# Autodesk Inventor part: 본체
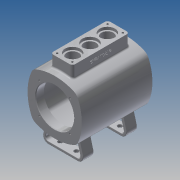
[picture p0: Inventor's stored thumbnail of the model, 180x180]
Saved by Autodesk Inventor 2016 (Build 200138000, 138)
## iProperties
Created: 2015-11
Part Number: 본체
Material: 알루미늄 6061
Document SubType Name: Modeling
Designer: mduedu
Density: 2.71 g/cm^3
Appearance: 알루미늄 - 평지
Mass: 1109.74 g
Surface Area: 1165.93 cm^2
Volume: 409.5 cm^3
Author: mduedu
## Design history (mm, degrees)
sketch "스케치2"
  geometry: L1 (0, 250)-(0, -250); L2 (250, 0)-(-250, 0); L3 (-50, 50)-(50, 50); L4 (50, 50)-(50, -50); L5 (50, -50)-(-50, -50); L6 (-50, -50)-(-50, 50); A1 r 90 centre (-40, 0) between (40.415, -40.415) and (40.415, 40.415); A2 r 90 centre (40, 0) between (-40.415, 40.415) and (-40.415, -40.415); A3 r 90 centre (0, -40) between (40.415, 40.415) and (-40.415, 40.415); A4 r 90 centre (0, 40) between (-40.415, -40.415) and (40.415, -40.415); 2 further points
  constraints: 12 end point, 8 point on circle, 4 centre point, 4 tangent, 3 perpendicular, 2 horizontal alignment, 2 midpoint, 2 parallel, 2 symmetric about line, 1 coincident, 1 equal radius, 1 horizontal, 1 vertical, 1 vertical alignment, 2 other
  dimensions: "d6" = 500 distance of L1.start L1.end; "d8" = 500 distance of L2.start L2.end; "d9" = 100 distance of L3.end L4.end; "d11" = 90 radius of A3
extrude "돌출1" new body sketch "스케치2" stored distance "d12" = 130; taper "d13" = 0 deg
fillet "모깎기6" dims "d30" = 15
feature "쉘1" dims "d31" = 15, "d32" = 6, "d33" = 15
sketch "스케치5"
  geometry: C1 r 35 at (0, 0); 1 further point
  constraints: 1 centre point, 1 coincident
  dimensions: "d34" = 70 diameter of C1
extrude "돌출3" cut sketch "스케치5" stored distance "d36" = 3; taper "d37" = 0 deg
fillet "모깎기14" dims "d78" = 3
sketch "스케치12"
  geometry: L1 (0, 0)-(28.284, 28.284); L2 (0, 0)-(40, 0); A1 r 40 centre (0, 0) between (28.284, 28.284) and (40, 0); 2 further points
  constraints: 4 end point, 2 coincident, 2 point on circle, 1 centre point, 1 horizontal
  dimensions: "d79" = 80 diameter of A1; "d80" = 45 deg angle of L2 L1
hole "구멍2" sketch "스케치12" at (28.284, 28.284) diameter "d82" = 3.242; stored, may be unused: countersink angle "d86" = 90 deg, drill point angle "d88" = 118 deg; dims "d83" = 9, "d84" = 10, "d85" = 2, "d87" = 11
node "작업 평면2"
sketch "스케치13"
  geometry: L1 (-52.5, -20)-(52.5, -20); L2 (52.5, -20)-(52.5, 20); L3 (52.5, 20)-(-52.5, 20); L4 (-52.5, 20)-(-52.5, -20); L5 (-52.5, -20)-(52.5, 20); L6 (52.5, -20)-(-52.5, 20); 1 further point
  constraints: 12 end point, 2 midpoint, 2 parallel, 1 horizontal, 1 perpendicular
  dimensions: "d93" = 105 distance of L2.end L3.end; "d95" = 40 distance of L1.end L2.end
extrude "돌출8" join sketch "스케치13" stored distance "d96" = 80; taper "d97" = 0 deg
fillet "모깎기15" dims "d98" = 5
fillet "모깎기16" dims "d99" = 3
sketch "스케치14"
  geometry: L1 (-52.5, 15)-(-52.5, -15) reference; L2 (52.5, -15)-(52.5, 15) reference; L3 (-52.5, 0)-(52.5, 0); 4 further points
  constraints: 2 end point, 2 midpoint, 2 point on line, 1 coincident
  dimensions: "d100" = 32 distance of point (-32, 0) point (0, 0); "d102" = 32 distance of point (32, 0) point (0, 0) (derived)
hole "구멍3" sketch "스케치14" at (-32, 0), (0, 0), (32, 0) diameter "d103" = 22; stored, may be unused: countersink angle "d107" = 90 deg, drill point angle "d109" = 118 deg; dims "d104" = 8, "d105" = 28, "d106" = 5, "d108" = 10
sketch "스케치15"
  geometry: L1 (46.5, -14)-(-46.5, -14); L2 (-46.5, -14)-(-46.5, 14); L3 (-46.5, 14)-(46.5, 14); L4 (46.5, 14)-(46.5, -14); L5 (46.5, -14)-(-46.5, 14); L6 (-46.5, -14)-(46.5, 14); L7 (47.5, 20)-(-47.5, 20) reference; L8 (-52.5, 15)-(-52.5, -15) reference; 5 further points
  constraints: 12 end point, 4 coincident, 2 midpoint, 2 parallel, 1 horizontal, 1 perpendicular
  dimensions: "d110" = 6 distance between parallel lines of L3 L7; "d111" = 6 distance between parallel lines of L2 L8
hole "구멍4" sketch "스케치15" at (-46.5, 14), (46.5, 14), (46.5, -14), (-46.5, -14) diameter "d112" = 3.242; stored, may be unused: countersink angle "d116" = 90 deg, drill point angle "d118" = 118 deg; dims "d113" = 10, "d114" = 28, "d115" = 5, "d117" = 13
sketch "스케치16"
  geometry: L1 (33.5, 0)-(61.5, 0) reference; 2 further points
  constraints: 1 vertical alignment, 1 other
  dimensions: "d128" = 11 distance from line of L1 point (47.5, -11)
feature "엠보싱2" sketch "스케치16" dims "d6" = 500, "d8" = 500, "d9" = 100, "d11" = 90, "d34" = 70, "d123" = 0.5, "d124" = 0
chamfer "모따기1" distance "d125" = 1; stored, may be unused: second distance "d126" = 2, angle "d127" = 45 deg
sketch "스케치18"
  geometry: L1 (0, 0)-(0, -80); L2 (40, -80)-(30.531, -44.663); L3 (-40, -80)-(-30.531, -44.663); L4 (-40, -80)-(40, -80); A1 r 90 centre (0, 40) between (-34.941, -42.941) and (34.941, -42.941) reference; A2 r 90 centre (0, 40) between (-30.531, -44.663) and (30.531, -44.663)
  constraints: 8 end point, 3 point on circle, 2 symmetric about line, 1 centre point, 1 coincident, 1 midpoint, 1 perpendicular, 1 vertical
  dimensions: "d132" = 80 distance of L3.start L2.start; "d134" = 75 deg angle of L4 L2; "d136" = 80 distance of L1.start L1.end
extrude "돌출9" new body sketch "스케치18" stored distance "d137" = 100; taper "d138" = 0 deg
fillet "모깎기17" dims "d139" = 10
sketch "스케치19"
  geometry: L1 (26.968, -80)-(-26.968, -80) reference; L2 (-36.627, -67.412)-(-30.531, -44.663) reference; L3 (30.531, -44.663)-(36.627, -67.412) reference; L4 (-25.775, -46.23)-(-31.797, -68.706); L5 (-26.968, -75)-(26.968, -75); L6 (31.797, -68.706)-(25.775, -46.23); L7 (0, 0)-(0, -80); A1 r 10 centre (26.968, -70) between (26.968, -80) and (36.627, -67.412) reference; A2 r 10 centre (-26.968, -70) between (-36.627, -67.412) and (-26.968, -80) reference; A3 r 90 centre (0, 40) between (-30.531, -44.663) and (30.531, -44.663) reference; A4 r 5 centre (-26.968, -70) between (-31.797, -68.706) and (-26.968, -75); A5 r 5 centre (26.968, -70) between (26.968, -75) and (31.797, -68.706); A6 r 90 centre (0, 40) between (-25.775, -46.23) and (25.775, -46.23)
  constraints: 8 end point, 7 point on circle, 3 centre point, 2 parallel, 1 coincident, 1 midpoint, 1 symmetric about line, 1 tangent, 2 other
  dimensions: "d140" = 5 distance between parallel lines of L1 L5
extrude "돌출10" cut sketch "스케치19" stored distance "d141" = 100; taper "d142" = 0 deg
sketch "스케치20"
  geometry: L1 (-30, 0)-(30, 0); L2 (30, 0)-(30, -90); L3 (30, -90)-(-30, -90); L4 (-30, -90)-(-30, 0); L5 (50, -80)-(-50, -80) reference; 2 further points
  constraints: 8 end point, 2 parallel, 1 coincident, 1 horizontal, 1 midpoint, 1 perpendicular
  dimensions: "d143" = 10 distance from line of L5 L2.end; "d144" = 60 distance of L2.end L3.end
extrude "돌출11" cut sketch "스케치20" stored distance "d145" = 100; taper "d146" = 0 deg
sketch "스케치21"
  geometry: L1 (0, 26.968)-(100, 26.968); L2 (100, 53.935)-(100, 0) reference; L3 (0, 0)-(0, 53.935) reference; L4 (0, 53.935)-(20, 53.935) reference; L5 (20, 0)-(0, 0) reference; L6 (115, 76.968)-(-15, 76.968) reference; L7 (115, -23.032)-(-15, -23.032) reference; L8 (10, 53.935)-(10, 0); L9 (50, 76.968)-(50, -23.032); C1 r 4 at (10, 41.968); C2 r 4 at (10, 11.968); C3 r 4 at (90, 41.968); C4 r 4 at (90, 11.968); 2 further points
  constraints: 6 end point, 6 midpoint, 4 centre point, 3 symmetric about line, 1 coincident, 1 horizontal, 1 point on line, 3 other
  dimensions: "d147" = 8 diameter of C1; "d148" = 15 distance from line of C1.centre L1
extrude "돌출12" cut sketch "스케치21" stored distance "d149" = 100; taper "d150" = 0 deg
feature "결합2"
  node "솔리드3"
fillet "모깎기18" dims "d151" = 1
fillet "모깎기19" dims "d152" = 2
node "솔리드1"
pattern_circular "원형 패턴1" dims angle "d90" = 360 deg
mirror "대칭3"
node "투영된 루프1"
